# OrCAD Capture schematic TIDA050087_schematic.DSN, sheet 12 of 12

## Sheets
12 P10: PMIC TI AND EXT REGULATOR: size C
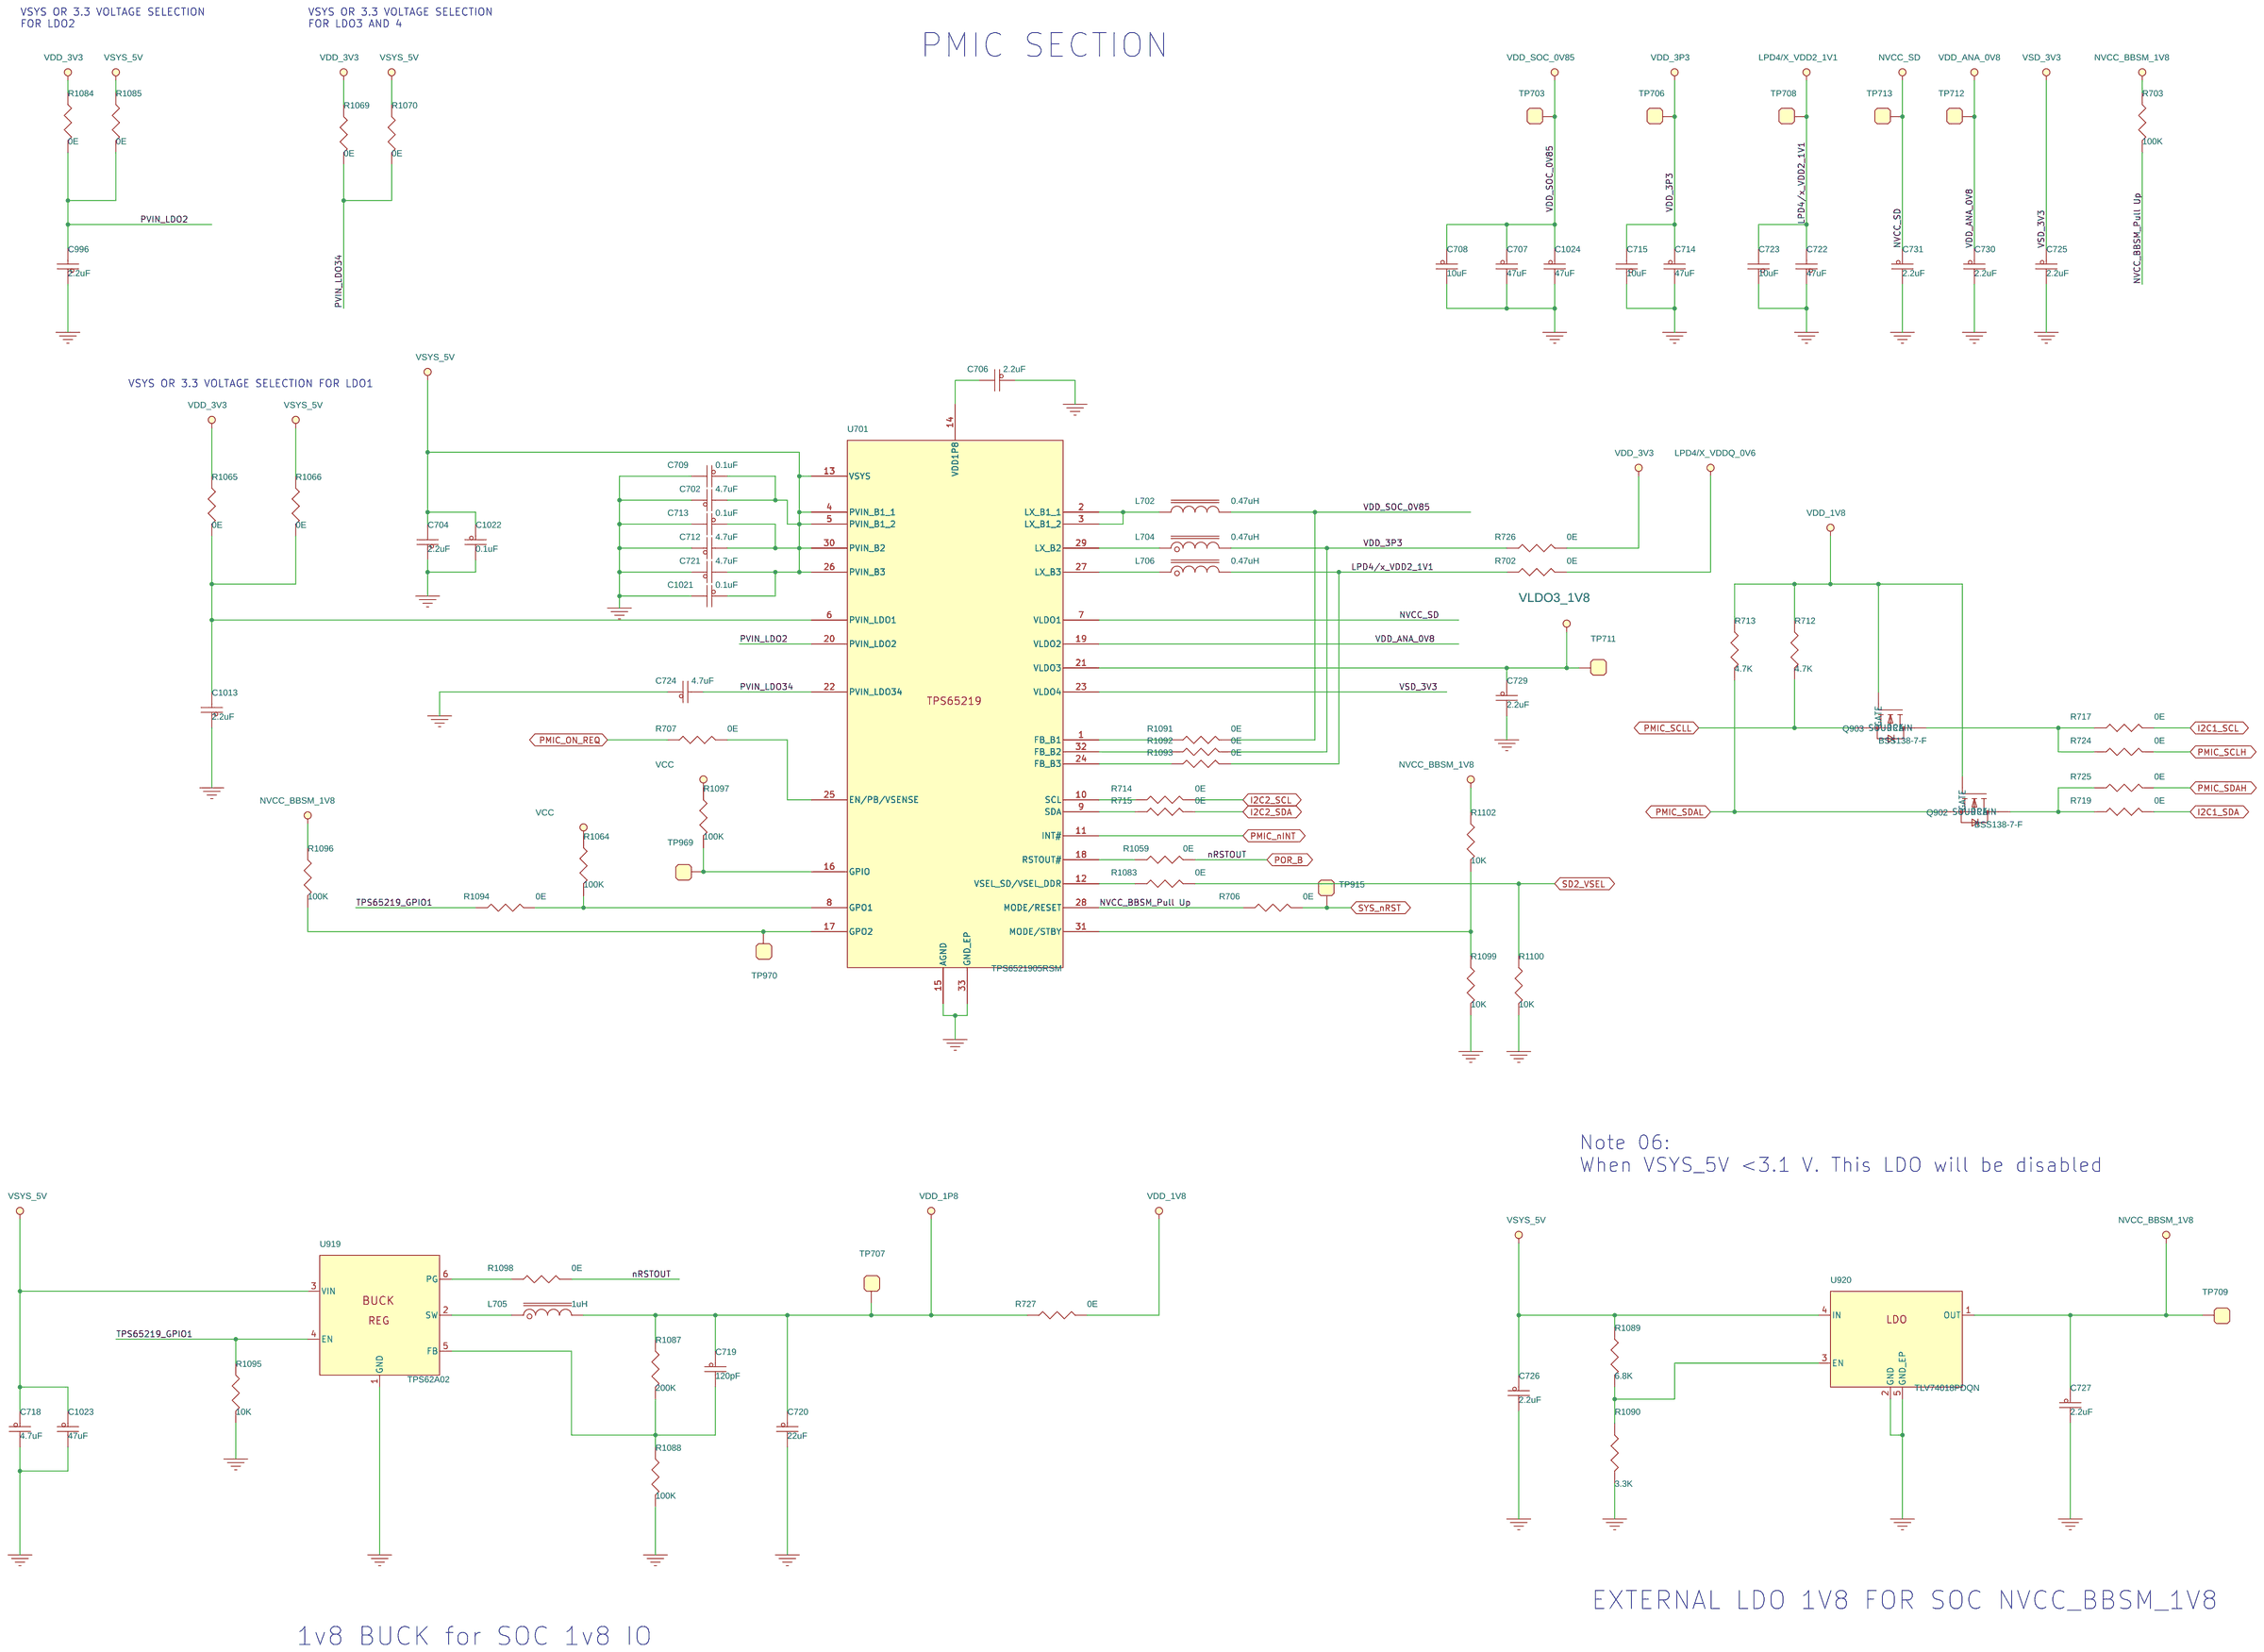
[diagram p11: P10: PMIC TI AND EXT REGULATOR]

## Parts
C702  4.7uF  [0805]
C704  2.2uF  [0603]
C706  2.2uF  [0402]
C707  47uF  [1206_T_A1]
C708  10uF  [0603]
C709  0.1uF  [0201]
C712  4.7uF  [0805]
C713  0.1uF  [0201]
C714  47uF  [1206_T_A1]
C715  10uF  [0603]
C718  4.7uF  [0805]
C719  120pF  [0603]
C720  22uF  [0805]
C721  4.7uF  [0805]
C722  47uF  [1206_T_A1]
C723  10uF  [0603]
C724  4.7uF  [0603]
C725  2.2uF  [0402]
C726  2.2uF  [0603]
C727  2.2uF  [0402]
C729  2.2uF  [0402]
C730  2.2uF  [0402]
C731  2.2uF  [0402]
C996  2.2uF  [0603]
C1013  2.2uF  [0603]
C1021  0.1uF  [0201]
C1022  0.1uF  [0201]
C1023  47uF  [0805]
C1024  47uF  [1206_T_A1]
L702  0.47uH  [IND2_3_3P5X3P2_B_A1]
L704  0.47uH  [IND2_1P8_2X1P2_POL_A1]
L705  1uH  [IND2_1P8_3P2X3P5_A_A1]
L706  0.47uH  [IND2_1P8_2X1P2_POL_A1]
Q902  BSS138-7-F  [SOT23-3L_1P9_2P9X1P3_A1]
Q903  BSS138-7-F  [SOT23-3L_1P9_2P9X1P3_A1]
R702  0E  [RC0603]
R703  100K  [0402]
R706  0E  [0201]
R707  0E  [0201]
R712  4.7K  [0402]
R713  4.7K  [0402]
R714  0E  [0201]
R715  0E  [0201]
R717  0E  [0201]
R719  0E  [0201]
R724  0E  [0201]
R725  0E  [0201]
R726  0E  [RC0805]
R727  0E  [RC0805]
R1059  0E  [0201]
R1064  100K  [0201]
R1065  0E  [0402]
R1066  0E  [0402]
R1069  0E  [0402]
R1070  0E  [0402]
R1083  0E  [0201]
R1084  0E  [0402]
R1085  0E  [0402]
R1087  200K  [0402]
R1088  100K  [0402]
R1089  6.8K  [0201]
R1090  3.3K  [0201]
R1091  0E  [0402]
R1092  0E  [0402]
R1093  0E  [0402]
R1094  0E  [0201]
R1095  10K  [0402]
R1096  100K  [0201]
R1097  100K  [0201]
R1098  0E  [0402]
R1099  10K  [0402]
R1100  10K  [0402]
R1102  10K  [0402]
TP703  SMD  [TP35_SMD]
TP706  SMD  [TP35_SMD]
TP707  SMD  [TP35_SMD]
TP708  SMD  [TP35_SMD]
TP709  SMD  [TP35_SMD]
TP711  SMD  [TP35_SMD]
TP712  SMD  [TP35_SMD]
TP713  SMD  [TP35_SMD]
TP915  SMD  [TP35_SMD]
TP969  SMD  [TP35_SMD]
TP970  SMD  [TP35_SMD]
U701  TPS6521905RSM  [VQFN32_0P4_4X4_EP_A1]
U919  TPS62A02  [SOT563-6L_0P5_1P6X1P2_A_A1]
U920  TLV74018PDQN  [X2SON4_0P65_1X1_EP_A1]

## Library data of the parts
C702 C712 C721 = CAP_NP: Cap, Cer-X7R, 4.7uF, 10V, 10%, 0805; EN: 102-1-05284; KEY Number: 102-1-05284@1; Mfg: MURATA MANUFACTURING CO,LTD; Mfg Part No: GRM21BR71A475KE51L; Part Status: 3SILVER; RoHS Status: RoHS; Temperature: -55°C to +125°C
C704 C726 C996 C1013 = CAP_NP: Cap, Cer-X6S, 2.2uF, 16V, 10%, 0603; EN: 102-1-04305; KEY Number: 102-1-04305@1; Mfg: MURATA MANUFACTURING CO,LTD; Mfg Part No: GRM188C81C225KA12D; Part Status: 3SILVER; RoHS Status: RoHS; Temperature: -55°C to +105°C
C706 C725 C727 C729-C731 = CAP_NP: Cap, Cer-X7S, 2.2uF, 10V, 10%, 0402; EN: 102-1-02330; KEY Number: 102-1-02330@1; Mfg: TDK CORPORATION; Mfg Part No: C1005X7S1A225K050BC; Part Status: 4GOLD; RoHS Status: RoHS, REACH, HalogenFree; Temperature: -55°C to +125°C
C707 C714 C722 C1024 = CAP_NP: Cap, Cer-X7S, 47uF, 6.3V, 20%, 1206; EN: 102-1-05285; KEY Number: 102-1-05285@1; Mfg: TDK CORPORATION; Mfg Part No: C3216X7S0J476M160AC; Part Status: 3SILVER; RoHS Status: RoHS; Temperature: -55°C to +125°C
C708 C715 C723 = CAP_NP: Cap, Cer-X5R, 10uF, 10V, 10%, 0603; EN: 102-1-00156; KEY Number: 102-1-00156@1; Mfg: TDK CORPORATION; Mfg Part No: C1608X5R1A106K080AC; Part Status: 3SILVER; Temperature: -55°C to +85°C
C709 C713 C1021 C1022 = CAP_NP: Cap, Cer-X5R, 0.1uF, 10V, 10%, 0201; EN: 102-1-05397; KEY Number: 102-1-05397@1; Mfg: MURATA MANUFACTURING CO,LTD; Mfg Part No: GRM033R61A104KE15D; Part Status: 3SILVER; RoHS Status: RoHS; Temperature: -55°C to +85°C
C718 = CAP_NP: Cap, Cer-X7R, 4.7uF, 10V, 10%, 0805; EN: 102-1-05950; KEY Number: 102-1-05950@3; Mfg: MURATA MANUFACTURING CO,LTD; Mfg Part No: GRM21BR71A475KA73L; Part Status: 3SILVER
C719 = CAP_NP: Cap, Cer-X7R, 120pF, 10V, 10%, 0603; EN: 102-1-00101; KEY Number: 102-1-00101@1; Mfg: KYOCERA AVX COMPONENTS CORPORATION; Mfg Part No: 0603ZC121KAT2A; Part Status: 3SILVER; Temperature: -55°C to +125°C
C720 = CAP_NP: Cap, Cer-X7R, 22uF, 10V, 20%, 0805; EN: 102-1-03822; KEY Number: 102-1-03822@1; Mfg: MURATA MANUFACTURING CO,LTD; Mfg Part No: GRM21BZ71A226ME15L; Part Status: 3SILVER; RoHS Status: RoHS; Temperature: -55°C to +125°C
C724 = CAP_NP: Cap, Cer-X7S, 4.7uF, 10V, 10%, 0603; EN: 102-1-07950; KEY Number: 102-1-07950@2; Mfg: TDK CORPORATION; Mfg Part No: C1608X7S1A475K080AC; Part Status: 3SILVER
C1023 = CAP_NP: Cap, Cer-X5R, 47uF, 6.3V, 20%, 0805; EN: 102-1-00038; KEY Number: 102-1-00038@1; Mfg: SAMSUNG ELECTRO-MECHANICS AMERICA, INC; Mfg Part No: CL21A476MQYNNNE; Part Status: 3SILVER; RoHS Status: ROHS; Temperature: -55°C to +85°C
L702 = IND_CORE_A: Ind, Power, 0.47uH, 20%, 7A, 23mE, Shielded, 105MHz, AEC-Q200, SMD; EN: 103-1-01757; KEY Number: 103-1-01757@1; Mfg: BOURNS INC; Mfg Part No: SRP3020TA-R47M; Part Status: 3SILVER; RoHS Status: RoHS; Temperature: -55°C to +150°C
L704 L706 = IND_CORE_POL_B: Ind, Power, 0.47uH, 20%, 4.2A, 29mE, Shielded, 1MHz, SMD; EN: 103-1-01877; KEY Number: 103-1-01877@1; Mfg: TDK CORPORATION; Mfg Part No: TFM201208BLE-R47MTCF; Part Status: 3SILVER; RoHS Status: RoHS; Temperature: -40°C to +125°C
L705 = IND_CORE_POL_B: Ind, Power, 1uH, 20%, 7.5A, 14.8mE, Shielded, 80MHz, AEC-Q200, SMD; EN: 103-1-01559; KEY Number: 103-1-01559@1; Mfg: COILCRAFT; Mfg Part No: XGL3520-102MEC; Part Status: 3SILVER; RoHS Status: RoHS, Halogen Free; Temperature: -40°C to +125°C
Q902 Q903 = TRANS_NMOS-ENX1_3P: Transistor, N-MOSFET, 50V, 0.2A, Vgs=20V, 0.3W, SOT23-3; EN: 107-2-01033; KEY Number: 107-2-01033@1; Mfg: DIODES INCORPORATED; Part Status: 3SILVER; RoHS Status: ROHS; Temperature: -55°C to +150°C
R702 = RES: Res, Chip, 0E, 1/10W, 1A, 0603; EN: 101-1-08684; KEY Number: 101-1-08684@1; Mfg: WALSIN TECHNOLOGY CORP.; Mfg Part No: WR06X000 PTL; Part Status: 3SILVER; RoHS Status: RoHS; Temperature: -55°C to +155°C
R703 = RES: Res, Chip, 100K, 1/16W, 5%, 0402; EN: 101-1-11924; KEY Number: 101-1-11924@1; Mfg: VENKEL CORP; Mfg Part No: CR0402-16W-104JT
R706 R707 R714 R715 R717 R719 R724 R725 R1059 R1083 R1094 = RES: Res, Chip, 0E, 1/20W, 1A, 0201; EN: 101-1-12661; KEY Number: 101-1-12661@1; Mfg: BOURNS INC; Mfg Part No: CR0201-J/-000GLF
R712 R713 = RES: Res, Chip, 4.7K, 1/10W, 5%, AEC-Q200, 0402; EN: 101-1-02785; KEY Number: 101-1-02785@1; Mfg: KOA SPEER ELECTRONICS, INC; Mfg Part No: RK73B1ETTP472J; Part Status: 3SILVER; RoHS Status: RoHS; Temperature: -55°C to +155°C
R726 R727 = RES: Res, Chip, 0E, 1/8W, 5A, 0805; EN: 101-1-03831; KEY Number: 101-1-03831@1; Mfg: YAGEO CORPORATION; Mfg Part No: RC0805JR-070RL; Part Status: 3SILVER; Temperature: -55°C to +155°C
R1064 R1096 R1097 = RES: Res, Chip, 100K, 1/20W, 1%, 0201; EN: 101-1-03797; KEY Number: 101-1-03797@1; Mfg: VISHAY INTERTECHNOLOGY, INC; Mfg Part No: CRCW0201100KFKED; Part Status: 3SILVER; RoHS Status: RoHS; Temperature: -55°C to +155°C
R1065 R1066 R1069 R1070 R1084 R1085 R1091-R1093 R1098 = RES: Res, Chip, 0E, 1/16W, 5%, 0402; EN: 101-1-08134; KEY Number: 101-1-08134@1; Mfg: YAGEO CORPORATION; Mfg Part No: RC0402JR-070RL; Part Status: 3SILVER; RoHS Status: RoHS; Temperature: -55°C to +155°C
R1087 = RES: Res, Chip, 200K, 1/16W, 1%, 0402; EN: 101-1-00514; KEY Number: 101-1-00514@1; Mfg: VISHAY INTERTECHNOLOGY, INC; Mfg Part No: CRCW0402200KFKEDC; Part Status: 3SILVER; RoHS Status: RoHS, Halogen Free; Temperature: -55°C to +155°C
R1088 = RES: Res, Chip, 100K, 1/16W, 1%, 0402; EN: 101-1-00485; KEY Number: 101-1-00485@1; Mfg: YAGEO CORPORATION; Mfg Part No: RC0402FR-07100KL; Part Status: 4GOLD; RoHS Status: RoHS, HalogenFree; Temperature: -55°C to +155°C
R1089 = RES: Res, Chip, 6.8K, 1/20W, 1%, 0201; EN: 101-1-06785; KEY Number: 101-1-06785@1; Mfg: VISHAY INTERTECHNOLOGY, INC; Mfg Part No: CRCW02016K80FNED; Part Status: 3SILVER; RoHS Status: RoHS; Temperature: -55°C to +155°C
R1090 = RES: Res, Chip, 3.3K, 1/20W, 1%, 0201; EN: 101-1-05219; KEY Number: 101-1-05219@1; Mfg: WALSIN TECHNOLOGY CORP.; Mfg Part No: WR02X3301 FAL; Part Status: 3SILVER; RoHS Status: Lead free; Temperature: -55°C to +125°C
R1095 R1099 R1100 R1102 = RES: Res, Chip, 10K, 1/16W, 5%, AEC-Q200, 0402; EN: 101-1-04836; KEY Number: 101-1-04836@1; Mfg: VISHAY INTERTECHNOLOGY, INC; Mfg Part No: CRCW040210K0JNED; Part Status: 3SILVER; Temperature: -55°C to +155°C
TP703 TP706-TP709 TP711-TP713 TP915 TP969 TP970 = TEST_POINT_SMD: Testpoint, Pad=0.89mm, SM=0.99mm, SMD; EN: 666-1-00039; KEY Number: 666-1-00039@1; Mfg: NA; Mfg Part No: 666-1-00039; Part Status: 3SILVER
U701 = IC_TPS65219_32P_EP_A1: IC, TPS6521905, PMIC, 7 Outputs, 3-DC/DC&4-LDOs, VQFN-32; EN: 301-4-03209; KEY Number: 301-4-03209@1; Mfg: TEXAS INSTRUMENTS; Mfg Part No: TPS6521905RSMR; Part Status: 3SILVER; RoHS Status: RoHS; Temperature: -40°C to +105°C
U919 = IC_SWITCHER_6P_Y_A1: IC, Switcher, 2.5-5.5Vin, 0.6-5.5Vout/2A, 2.4MHz, Sync Buck Conv, SOT-563-6; EN: 301-4-02742; KEY Number: 301-4-02742@1; Mfg: TEXAS INSTRUMENTS; Mfg Part No: TPS62A02DRLR; Part Status: 3SILVER; RoHS Status: RoHS; Temperature: -40°C to +125°C
U920 = IC_LDO-FIXED_4P_EP_A_A2: IC, LDO, 1.4-5.5Vin, 1.8Vout/0.3A, X2SON-4; EN: 301-4-02010; KEY Number: 301-4-02010@1; Mfg: TEXAS INSTRUMENTS; Mfg Part No: TLV74018PDQNR; Part Status: 3SILVER; RoHS Status: RoHS; Temperature: -40°C to +125°C

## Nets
GND: C702.1 C704.1 C706.1 C707.2 C708.2 C709.2 C712.1 C713.2 C714.2 C715.1 C718.2 C720.2 C721.1 C722.1 C723.1 C724.1 C725.2 C726.2 C727.2 C729.2 C730.2 C731.2 C996.1 C1013.1 C1021.2 C1022.2 C1023.2 C1024.2 R1088.2 R1090.2 R1095.2 R1099.2 R1100.2 U701.15(AGND) U701.33(GND_EP) U919.1(GND) U920.2(GND) U920.5(GND_EP) ; also on sheet 1 2 3 5 6 7 8 10
PVIN_LDO2: C996.2 R1084.2 R1085.2 U701.20(PVIN_LDO2)
PVIN_LDO34: C724.2 R1069.2 R1070.2 U701.22(PVIN_LDO34)
VDD_1P8: C719.1 C720.1 L705.2 R727.1 R1087.1 TP707.1 ; also on sheet 10
VDD_1V8: Q902.1(GATE) Q903.1(GATE) R712.1 R713.1 R727.2 ; also on sheet 2 3 5 6 10
VDD_3P3: C714.1 C715.2 L704.2 R726.1 R1092.2 TP706.1 ; also on sheet 10
VDD_3V3: R726.2 R1065.1 R1069.1 R1084.1 ; also on sheet 3 5 6 7 10
VDD_ANA_0V8: C730.1 TP712.1 U701.19(VLDO2) ; also on sheet 6 10
VDD_SOC_0V85: C707.1 C708.1 C1024.1 L702.2 R1091.2 TP703.1 ; also on sheet 6 10
I2C1_SCL: R717.2 ; also on sheet 5 8
I2C1_SDA: R719.2 ; also on sheet 5 8
I2C2_SCL: R714.2 ; also on sheet 5 8
I2C2_SDA: R715.2 ; also on sheet 5 8
LPD4/x_VDD2_1V1: C722.2 C723.2 L706.2 R702.1 R1093.2 TP708.1 ; also on sheet 2 6 10
LPD4/x_VDDQ_0V6: R702.2 ; also on sheet 2 6 10
NVCC_BBSM_1V8: C727.1 R703.1 R1064.1 R1096.1 R1097.1 R1102.1 TP709.1 U920.1(OUT) ; also on sheet 1 5 6 10
NVCC_BBSM_Pull Up: R703.2 R706.1 U701.28(MODE/RESET)
NVCC_SD: C731.1 TP713.1 U701.7(VLDO1) ; also on sheet 6 10
PMIC_nINT: U701.11(INT#) ; also on sheet 5
PMIC_ON_REQ: R707.1 ; also on sheet 1 5
PMIC_SCLH: R724.2 ; also on sheet 5
PMIC_SCLL: Q903.2(SOURCE) R712.2 ; also on sheet 5
PMIC_SDAH: R725.2 ; also on sheet 5
PMIC_SDAL: Q902.2(SOURCE) R713.2 ; also on sheet 5
POR_B: R1059.2 R1098.2 ; also on sheet 1 5 10
SD2_VSEL: R1083.2 R1100.1 ; also on sheet 8
SYS_nRST: R706.2 TP915.1 ; also on sheet 5
TPS65219_GPIO1: R1094.1 R1095.1 U919.4(EN)
VLDO3_1V8: C729.1 TP711.1 U701.21(VLDO3) ; also on sheet 6
VSD_3V3: C725.1 U701.23(VLDO4) ; also on sheet 5 10
VSYS_5V: C702.2 C704.2 C709.1 C712.2 C713.1 C718.1 C721.2 C726.1 C1021.1 C1022.1 C1023.1 R1066.1 R1070.1 R1085.1 R1089.1 U701.4(PVIN_B1_1) U701.5(PVIN_B1_2) U701.13(VSYS) U701.26(PVIN_B3) U701.30(PVIN_B2) U919.3(VIN) U920.4(IN) ; also on sheet 5 7 10
N116434057: C706.2 U701.14(VDD1P8)
N116434617: R707.2 U701.25(EN/PB/VSENSE)
N116434822: L702.1 U701.2(LX_B1_1) U701.3(LX_B1_2)
N116434898: L704.1 U701.29(LX_B2)
N116434901: L706.1 U701.27(LX_B3)
N116471687: R1059.1 U701.18(RSTOUT#)
N116471690: R1083.1 U701.12(VSEL_SD/VSEL_DDR)
N116476004: C1013.2 R1065.2 R1066.2 U701.6(PVIN_LDO1)
N116660464: R714.1 U701.10(SCL)
N116660470: R715.1 U701.9(SDA)
N116772045: L705.1 U919.2(SW)
N116772074: C719.2 R1087.2 R1088.1 U919.5(FB)
N116772436: R1089.2 R1090.1 U920.3(EN)
N116861023: Q903.3(DRAIN) R717.1 R724.1
N116861029: Q902.3(DRAIN) R719.1 R725.1
N116892698: R1097.2 TP969.1 U701.16(GPIO)
N116924893: R1091.1 U701.1(FB_B1)
N116924896: R1092.1 U701.32(FB_B2)
N116924899: R1093.1 U701.24(FB_B3)
N116925021: R1099.1 R1102.2 U701.31(MODE/STBY)
N116939248: R1064.2 R1094.2 U701.8(GPO1)
N116980775: R1096.2 TP970.1 U701.17(GPO2)
N116981199: R1098.1 U919.6(PG)

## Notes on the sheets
sheet 12
- VSYS OR 3.3 VOLTAGE SELECTION
  FOR LDO2
- VSYS OR 3.3 VOLTAGE SELECTION
  FOR LDO3 AND 4
- PMIC SECTION
- VSYS OR 3.3 VOLTAGE SELECTION FOR LDO1
- Note 06:
  When VSYS_5V <3.1 V. This LDO will be disabled
- EXTERNAL LDO 1V8 FOR SOC NVCC_BBSM_1V8
- 1v8 BUCK for SOC 1v8 IO
